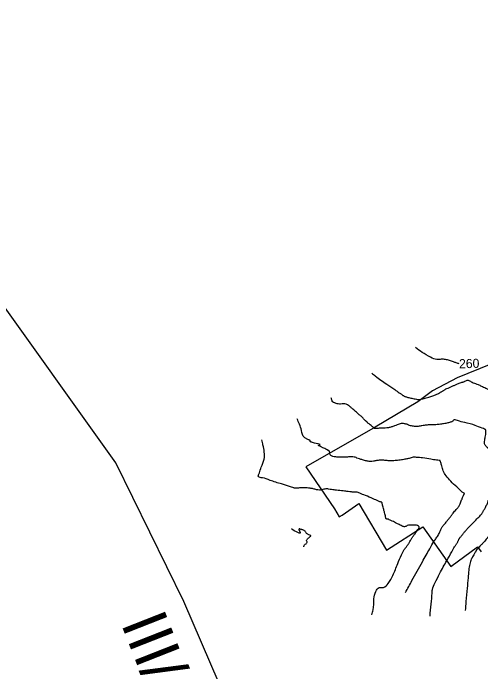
# Model space of a CAD drawing. Extents: x -478232 to -472707, y -1118753 to -1113967.
# Drawn here: x -476569.9 to -476364.6, y -1115588.3 to -1115298.9 of the extents above; entities that cross this region are included whole.
import ezdxf

# ---------------------------------------------------------------- set-up
doc = ezdxf.new("R2010")
doc.units = 0
for name, color, linetype in [('ObPÚ', 7, 'Continuous'), ('silnice', 7, 'Continuous'), ('Vrstevnice_hlavni', 7, 'Continuous'), ('Vrstevnice_popis', 7, 'Continuous'), ('Vrstevnice_vedlejsi', 7, 'Continuous')]:
    doc.layers.add(name, color=color, linetype=linetype)

msp = doc.modelspace()

# ---------------------------------------------------------------- linework, layer by layer
at = {"layer": 'ObPÚ'}
msp.add_lwpolyline([(-476350.14, -1115449), (-476375.02, -1115459.02), (-476385.85, -1115464.8), (-476392.23, -1115469.66), (-476411.03, -1115480.79), (-476441.42, -1115498.26), (-476428.9, -1115516.62), (-476426.71, -1115520.24), (-476425.46, -1115519.42), (-476418.11, -1115514.37), (-476406.06, -1115534.8), (-476390, -1115524.57), (-476377.76, -1115542), (-476366.06, -1115533.41), (-476364.38, -1115535.62)], dxfattribs=at)
at = {"layer": 'silnice'}
msp.add_lwpolyline([(-476261.922, -1115907.288), (-476366.595, -1115823.727), (-476390.845, -1115803.24), (-476425.665, -1115718.481), (-476494.983, -1115557.356), (-476524.795, -1115496.42), (-476580.823, -1115418.032), (-476641.911, -1115352.297), (-476741.891, -1115268.259), (-476824.194, -1115202.313), (-477005.33, -1115056.573), (-477039.82, -1115023.276), (-477040.729, -1115022.048)], dxfattribs=at)
at = {"layer": 'Vrstevnice_hlavni'}
for points in [[(-476374.118, -1115452.894), (-476374.632, -1115452.768), (-476375.379, -1115452.515), (-476376.616, -1115452.074), (-476378.342, -1115451.442), (-476380.123, -1115451.064), (-476381.96, -1115450.937), (-476383.851, -1115451.062), (-476386.654, -1115450.049), (-476390.368, -1115447.898), (-476393.306, -1115445.807)], [(-476442.249, -1115533.315), (-476442.258, -1115533.223), (-476442.035, -1115532.45), (-476441.322, -1115531.991), (-476440.926, -1115531.554), (-476440.848, -1115531.138), (-476441.086, -1115530.744), (-476441.04, -1115530.317), (-476440.708, -1115529.858), (-476440.091, -1115529.366), (-476439.638, -1115528.987), (-476439.349, -1115528.72), (-476439.224, -1115528.565), (-476439.347, -1115528.386), (-476439.718, -1115528.183), (-476440.335, -1115527.956), (-476440.852, -1115527.632), (-476441.268, -1115527.211), (-476441.584, -1115526.693), (-476441.969, -1115526.298), (-476442.426, -1115526.027), (-476442.953, -1115525.878), (-476443.443, -1115525.735), (-476443.895, -1115525.597), (-476444.309, -1115525.465), (-476444.44, -1115525.662), (-476444.286, -1115526.188), (-476443.849, -1115527.043), (-476447.74, -1115525.503)]]:
    msp.add_spline(points, degree=3, dxfattribs=at)
at = {"layer": 'Vrstevnice_vedlejsi'}
for points in [[(-476412.487, -1115456.977), (-476410.913, -1115458.262), (-476405.882, -1115461.815), (-476402.37, -1115464.29), (-476400.376, -1115465.685), (-476399.9, -1115466), (-476399.472, -1115466.293), (-476399.093, -1115466.564), (-476398.763, -1115466.813), (-476398.4, -1115467.035), (-476398.006, -1115467.232), (-476397.581, -1115467.402), (-476397, -1115467.583), (-476396.264, -1115467.775), (-476395.373, -1115467.977), (-476394.42, -1115468.176), (-476393.405, -1115468.369), (-476392.328, -1115468.558), (-476390.887, -1115468.463), (-476389.082, -1115468.084), (-476386.914, -1115467.422), (-476385.197, -1115466.84), (-476383.932, -1115466.337), (-476383.118, -1115465.915), (-476382.467, -1115465.566), (-476381.978, -1115465.291), (-476381.65, -1115465.088), (-476381.304, -1115464.864), (-476380.937, -1115464.618), (-476380.551, -1115464.349), (-476379.903, -1115463.998), (-476378.994, -1115463.563), (-476377.824, -1115463.044), (-476376.623, -1115462.523), (-476375.392, -1115462)], [(-476375.392, -1115462), (-476374.129, -1115461.473), (-476373.218, -1115461.118), (-476372.659, -1115460.933), (-476372.45, -1115460.919), (-476372.087, -1115460.802), (-476371.568, -1115460.58), (-476370.895, -1115460.255), (-476370.204, -1115460.181), (-476369.496, -1115460.36), (-476368.77, -1115460.791), (-476367.914, -1115461.219), (-476366.926, -1115461.642), (-476365.807, -1115462.062), (-476364.304, -1115462.716), (-476362.417, -1115463.605), (-476360.145, -1115464.728), (-476357.641, -1115465.438), (-476354.904, -1115465.734), (-476351.935, -1115465.618), (-476349.849, -1115465.502), (-476348.647, -1115465.387), (-476348.329, -1115465.272), (-476347.968, -1115465.34), (-476347.565, -1115465.59), (-476347.119, -1115466.023), (-476346.516, -1115466.573), (-476345.755, -1115467.242), (-476344.837, -1115468.03), (-476344.033, -1115469.141), (-476343.343, -1115470.576), (-476342.768, -1115472.335), (-476342.342, -1115473.633), (-476342.065, -1115474.468), (-476341.938, -1115474.841), (-476341.36, -1115475.721), (-476340.333, -1115477.106), (-476338.856, -1115478.997), (-476337.825, -1115480.446), (-476337.242, -1115481.454), (-476337.106, -1115482.02), (-476336.708, -1115482.699), (-476336.047, -1115483.489), (-476335.123, -1115484.392), (-476334.613, -1115485.234), (-476334.515, -1115486.014), (-476334.83, -1115486.732), (-476335.165, -1115487.505), (-476335.519, -1115488.332), (-476335.893, -1115489.212), (-476336.181, -1115489.954), (-476336.384, -1115490.556), (-476336.5, -1115491.018), (-476336.678, -1115491.638), (-476336.918, -1115492.417), (-476337.22, -1115493.354), (-476337.658, -1115494.21), (-476338.234, -1115494.984), (-476338.946, -1115495.678), (-476339.549, -1115496.226), (-476340.042, -1115496.627), (-476340.425, -1115496.883), (-476340.759, -1115497.34), (-476341.045, -1115497.997), (-476341.282, -1115498.856), (-476341.828, -1115499.854), (-476342.682, -1115500.993), (-476343.846, -1115502.272), (-476344.811, -1115503.411), (-476345.578, -1115504.411), (-476346.146, -1115505.272), (-476346.807, -1115506.216), (-476347.56, -1115507.242), (-476348.405, -1115508.352), (-476349.595, -1115510.321), (-476351.128, -1115513.152), (-476353.005, -1115516.842), (-476354.314, -1115519.344), (-476355.055, -1115520.656), (-476355.227, -1115520.78), (-476355.538, -1115521.104), (-476355.989, -1115521.629), (-476356.58, -1115522.354), (-476357.559, -1115523.662), (-476358.927, -1115525.554), (-476360.684, -1115528.028), (-476362.218, -1115530.038), (-476363.528, -1115531.584), (-476364.614, -1115532.666), (-476365.375, -1115533.438), (-476365.811, -1115533.898), (-476365.922, -1115534.047), (-476366.035, -1115534.195), (-476366.151, -1115534.34), (-476366.269, -1115534.483), (-476366.37, -1115534.607), (-476366.453, -1115534.711)], [(-476390.415, -1115480.123), (-476392.093, -1115480.442), (-476393.773, -1115480.449), (-476395.455, -1115480.141), (-476397.138, -1115479.52), (-476398.521, -1115479.202), (-476399.606, -1115479.187), (-476400.391, -1115479.474), (-476401.353, -1115479.819), (-476402.494, -1115480.221), (-476403.813, -1115480.681), (-476405.189, -1115481.004), (-476406.622, -1115481.191), (-476408.113, -1115481.24), (-476409.287, -1115481.28), (-476410.144, -1115481.31), (-476410.685, -1115481.331), (-476411.093, -1115481.319), (-476411.368, -1115481.273), (-476411.51, -1115481.194), (-476411.664, -1115481.065), (-476411.83, -1115480.886), (-476412.009, -1115480.658), (-476412.452, -1115480.262), (-476413.159, -1115479.699), (-476414.132, -1115478.968), (-476414.756, -1115478.466), (-476415.033, -1115478.195), (-476414.961, -1115478.152), (-476415.298, -1115477.773), (-476416.042, -1115477.057), (-476417.195, -1115476.004), (-476418.233, -1115475.067), (-476419.157, -1115474.246), (-476419.967, -1115473.541), (-476420.822, -1115472.803), (-476421.721, -1115472.032), (-476422.665, -1115471.228), (-476423.717, -1115470.72), (-476424.877, -1115470.508), (-476426.145, -1115470.593), (-476427.196, -1115470.561), (-476428.028, -1115470.413), (-476428.643, -1115470.148), (-476429.106, -1115469.938), (-476429.418, -1115469.785), (-476429.579, -1115469.688), (-476430.087, -1115468.492), (-476430.298, -1115467.927)], [(-476435.156, -1115488.388), (-476435.158, -1115488.388), (-476435.557, -1115488.278), (-476436.352, -1115488.058), (-476437.543, -1115487.729), (-476438.431, -1115487.476), (-476439.016, -1115487.299), (-476439.298, -1115487.198), (-476439.46, -1115487.083), (-476439.502, -1115486.954), (-476439.423, -1115486.81), (-476439.571, -1115486.628), (-476439.947, -1115486.406), (-476440.549, -1115486.147), (-476441.093, -1115485.887), (-476441.577, -1115485.629), (-476442.002, -1115485.371), (-476443.347, -1115482.202), (-476445.27, -1115477.051)], [(-476386.868, -1115563.77), (-476386.404, -1115558.49), (-476385.983, -1115553.73), (-476385.843, -1115552.17), (-476384.718, -1115549.256), (-476382.607, -1115544.988), (-476379.51, -1115539.367), (-476377.347, -1115535.488), (-476376.117, -1115533.352), (-476375.821, -1115532.959), (-476375.527, -1115532.539), (-476375.236, -1115532.091), (-476374.948, -1115531.616), (-476374.711, -1115531.173), (-476374.526, -1115530.763), (-476374.393, -1115530.385), (-476374.22, -1115530.026), (-476374.008, -1115529.686), (-476373.756, -1115529.365), (-476373.437, -1115528.968), (-476373.052, -1115528.496), (-476372.6, -1115527.948), (-476372.158, -1115527.393), (-476371.726, -1115526.831), (-476371.304, -1115526.261), (-476370.255, -1115525.116), (-476368.58, -1115523.398), (-476366.278, -1115521.105), (-476364.681, -1115519.417), (-476363.788, -1115518.333), (-476363.599, -1115517.854), (-476363.38, -1115517.403), (-476363.131, -1115516.981), (-476362.852, -1115516.586), (-476362.624, -1115516.208), (-476362.447, -1115515.848), (-476362.32, -1115515.506), (-476362.183, -1115515.228), (-476362.036, -1115515.015), (-476361.879, -1115514.866), (-476361.743, -1115514.589), (-476361.628, -1115514.182), (-476361.535, -1115513.647), (-476361.302, -1115513.008), (-476360.931, -1115512.265), (-476360.421, -1115511.418), (-476359.844, -1115510.674), (-476359.201, -1115510.032), (-476358.493, -1115509.493), (-476357.886, -1115508.861), (-476357.381, -1115508.138), (-476356.978, -1115507.323), (-476356.457, -1115506.284), (-476355.818, -1115505.02), (-476355.061, -1115503.532), (-476354.274, -1115502.169), (-476353.457, -1115500.932), (-476352.611, -1115499.821), (-476352.458, -1115498.76), (-476353, -1115497.749), (-476354.236, -1115496.789), (-476355.796, -1115495.443), (-476357.679, -1115493.713), (-476359.885, -1115491.598), (-476361.477, -1115490.015), (-476362.455, -1115488.962), (-476362.82, -1115488.441), (-476362.968, -1115487.633), (-476362.899, -1115486.539), (-476362.614, -1115485.158), (-476362.433, -1115483.976), (-476362.356, -1115482.993), (-476362.383, -1115482.21), (-476363.943, -1115481.232), (-476367.039, -1115480.058), (-476371.668, -1115478.69), (-476374.855, -1115477.913), (-476376.599, -1115477.729), (-476376.9, -1115478.137), (-476377.722, -1115478.533), (-476379.064, -1115478.919), (-476380.926, -1115479.294), (-476382.829, -1115479.558), (-476384.771, -1115479.713), (-476386.754, -1115479.758), (-476388.635, -1115479.895), (-476390.415, -1115480.123)], [(-476408.095, -1115513.705), (-476408.196, -1115513.728), (-476408.268, -1115513.743), (-476408.31, -1115513.748), (-476408.321, -1115513.745), (-476409.488, -1115513.249), (-476411.808, -1115512.262), (-476415.283, -1115510.782), (-476417.744, -1115509.807), (-476419.192, -1115509.336), (-476419.626, -1115509.37), (-476420.137, -1115509.365), (-476420.725, -1115509.322), (-476421.39, -1115509.24), (-476422.819, -1115509.072), (-476425.012, -1115508.818), (-476427.967, -1115508.478), (-476430.119, -1115508.208), (-476431.467, -1115508.009), (-476432.012, -1115507.881), (-476432.677, -1115507.898), (-476433.462, -1115508.059), (-476434.367, -1115508.365), (-476435.455, -1115508.435), (-476436.726, -1115508.27), (-476438.179, -1115507.87), (-476439.551, -1115507.597), (-476440.841, -1115507.45), (-476442.049, -1115507.43), (-476443.148, -1115507.446), (-476444.139, -1115507.499), (-476445.02, -1115507.589), (-476445.738, -1115507.612), (-476446.294, -1115507.568), (-476446.687, -1115507.457), (-476448.623, -1115506.848), (-476452.103, -1115505.741), (-476457.127, -1115504.136), (-476460.496, -1115503.043), (-476462.21, -1115502.463), (-476462.27, -1115502.394), (-476462.297, -1115502.311), (-476462.291, -1115502.212), (-476462.252, -1115502.098), (-476461.808, -1115500.826), (-476460.959, -1115498.396), (-476459.705, -1115494.808), (-476460.221, -1115488.599), (-476460.746, -1115486.336)], [(-476381.496, -1115524.576), (-476381.058, -1115524.018), (-476380.504, -1115523.329), (-476379.834, -1115522.508), (-476379.049, -1115521.557), (-476378.281, -1115520.592), (-476377.53, -1115519.614), (-476376.797, -1115518.624), (-476376.099, -1115517.755), (-476375.438, -1115517.009), (-476374.812, -1115516.386), (-476374.17, -1115515.401), (-476373.512, -1115514.054), (-476372.838, -1115512.345), (-476372.335, -1115511.13), (-476372.003, -1115510.408), (-476371.84, -1115510.178), (-476371.827, -1115509.979), (-476371.962, -1115509.811), (-476372.246, -1115509.672), (-476373.318, -1115508.746), (-476375.177, -1115507.032), (-476377.825, -1115504.531), (-476379.802, -1115502.156), (-476381.109, -1115499.909), (-476381.745, -1115497.789), (-476382.17, -1115496.348), (-476382.383, -1115495.585), (-476382.386, -1115495.5), (-476382.424, -1115495.445), (-476382.499, -1115495.418), (-476382.61, -1115495.421), (-476382.691, -1115495.424), (-476382.74, -1115495.427), (-476382.759, -1115495.431), (-476382.784, -1115495.429), (-476382.813, -1115495.421), (-476382.848, -1115495.408), (-476384.079, -1115495.216), (-476386.506, -1115494.845), (-476390.13, -1115494.294), (-476392.866, -1115494.036), (-476394.717, -1115494.071), (-476395.681, -1115494.399), (-476397.081, -1115494.728), (-476398.917, -1115495.058), (-476401.19, -1115495.39), (-476403.316, -1115495.546), (-476405.295, -1115495.527), (-476407.128, -1115495.333), (-476408.815, -1115495.309), (-476410.355, -1115495.455), (-476411.749, -1115495.772), (-476413.243, -1115495.824), (-476414.837, -1115495.61), (-476416.531, -1115495.132), (-476417.908, -1115494.707), (-476418.968, -1115494.337), (-476419.711, -1115494.02), (-476420.805, -1115493.856), (-476422.249, -1115493.843), (-476424.045, -1115493.982), (-476425.766, -1115494.011), (-476427.414, -1115493.928), (-476428.987, -1115493.735), (-476430.078, -1115493.424), (-476430.686, -1115492.995), (-476430.812, -1115492.449), (-476430.915, -1115491.994), (-476430.996, -1115491.631), (-476431.055, -1115491.359), (-476431.167, -1115491.175), (-476431.332, -1115491.079), (-476431.551, -1115491.071), (-476431.695, -1115491.04), (-476431.765, -1115490.986), (-476431.759, -1115490.908), (-476432.056, -1115490.718), (-476432.657, -1115490.416), (-476433.561, -1115490.002), (-476434.225, -1115489.683), (-476434.65, -1115489.461), (-476434.835, -1115489.334), (-476434.976, -1115489.24), (-476435.074, -1115489.18), (-476435.128, -1115489.153), (-476435.254, -1115489.108), (-476435.453, -1115489.045), (-476435.725, -1115488.965), (-476435.863, -1115488.891), (-476435.867, -1115488.824), (-476435.736, -1115488.763), (-476435.599, -1115488.688), (-476435.455, -1115488.598), (-476435.304, -1115488.493), (-476435.204, -1115488.423), (-476435.156, -1115488.388)], [(-476412.508, -1115563.171), (-476411.848, -1115561.069), (-476411.539, -1115556.209), (-476410.675, -1115552.946), (-476409.255, -1115551.281), (-476407.279, -1115551.213), (-476405.259, -1115549.425), (-476403.194, -1115545.916), (-476401.086, -1115540.688), (-476399.421, -1115536.885), (-476398.2, -1115534.51), (-476397.423, -1115533.561), (-476396.715, -1115532.584), (-476396.077, -1115531.58), (-476395.509, -1115530.549), (-476394.886, -1115529.538), (-476394.208, -1115528.545), (-476393.474, -1115527.573), (-476392.807, -1115526.632), (-476392.208, -1115525.724), (-476391.677, -1115524.848), (-476391.892, -1115524.233), (-476392.853, -1115523.879), (-476394.56, -1115523.785), (-476395.9, -1115523.836), (-476396.873, -1115524.031), (-476397.48, -1115524.372), (-476398.046, -1115524.521), (-476398.573, -1115524.479), (-476399.059, -1115524.246), (-476400.034, -1115523.767), (-476401.498, -1115523.043), (-476403.451, -1115522.073), (-476404.773, -1115521.441), (-476405.463, -1115521.147), (-476405.521, -1115521.191), (-476405.642, -1115521.2), (-476405.825, -1115521.174), (-476406.072, -1115521.112), (-476406.25, -1115520.912), (-476406.358, -1115520.574), (-476406.399, -1115520.096), (-476406.555, -1115519.343), (-476406.827, -1115518.313), (-476407.215, -1115517.007), (-476407.516, -1115515.936), (-476407.728, -1115515.1), (-476407.853, -1115514.499), (-476407.938, -1115514.074), (-476407.983, -1115513.826), (-476407.988, -1115513.754), (-476408.025, -1115513.714), (-476408.095, -1115513.705)], [(-476397.702, -1115553.445), (-476394.813, -1115548.217), (-476390.245, -1115539.924), (-476387.028, -1115534.168), (-476385.162, -1115530.949), (-476384.647, -1115530.266), (-476384.137, -1115529.535), (-476383.631, -1115528.757), (-476383.13, -1115527.931), (-476382.719, -1115527.161), (-476382.397, -1115526.448), (-476382.166, -1115525.791), (-476381.866, -1115525.167), (-476381.496, -1115524.576)], [(-476366.453, -1115534.711), (-476366.519, -1115534.795), (-476366.575, -1115534.884), (-476366.62, -1115534.978), (-476366.655, -1115535.077), (-476366.704, -1115535.185), (-476366.766, -1115535.301), (-476366.841, -1115535.425), (-476366.917, -1115535.543), (-476366.994, -1115535.653), (-476367.072, -1115535.756), (-476367.394, -1115536.315), (-476367.961, -1115537.331), (-476368.772, -1115538.804), (-476369.413, -1115540.903), (-476369.885, -1115543.629), (-476370.186, -1115546.981), (-476370.595, -1115551.582), (-476371.111, -1115557.431), (-476371.459, -1115561.384)]]:
    msp.add_spline(points, degree=3, dxfattribs=at)

# ---------------------------------------------------------------- texts
at = {"layer": 'silnice'}
msp.add_text('III/48615', height=20, rotation=291.50868, dxfattribs=at).set_placement((-476522.739, -1115566.913))
at = {"layer": 'Vrstevnice_popis'}
msp.add_text(' 260 ', height=4, rotation=1.48492, dxfattribs=at).set_placement((-476375.588, -1115454.953))

doc.saveas('drawing.dxf')
